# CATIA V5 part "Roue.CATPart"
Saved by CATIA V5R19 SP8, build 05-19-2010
Part number: Roue
Bounding box of the stored display mesh (mm): x -500 to 275, y -874.961 to 874.961, z -874.961 to 874.961
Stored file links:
  C:\Users\rcousturie\Desktop\EU_thinkMotion\iao\IAO_MMS_Groupe1\flacan\flacan\flacan\Roue.CATPart
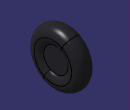
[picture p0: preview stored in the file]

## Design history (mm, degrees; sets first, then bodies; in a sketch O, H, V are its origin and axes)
Body1 (main body)
  Sketch1 on yz-plane, origin (0, 0, 0), H (0, 1, 0), V (0, 0, 1)
    circle A1 centre (0, 0) radius 600
    radius A1 = 600
  Pad1: profile Sketch1, direction (1, 0, 0), length 175, opposite side length 175
  Sketch2 on zx-plane, origin (0, 0, 0), H (-1, 0, 0), V (0, 0, 1)
    circle A1 centre (0, 600) radius 275
    point P1 (0, 600)
    radius A1 = 275
    distance P1 H = 600
    coincidence: P1 V
  Shaft1: profile Sketch2, axis Sketch2.H, angle 360
  Sketch3 on start face of Pad1, origin (-175, 0, 0), H (0, -1, 0), V (0, 0, 1)
    circle A1 centre (0, 0) radius 175
    radius A1 = 175
  Pad2: profile Sketch3, direction (-1, 0, 0), length 150
  Sketch4 on end face of Pad2, origin (-325, 0, 0), H (0, -1, 0), V (0, 0, 1)
    circle A1 centre (0, 0) radius 87.5
    point P1 (-87.5, 0)
    radius A1 = 87.5
    coincidence: A1 P1, P1 H
  Pad3: profile Sketch4, direction (-1, 0, 0), length 175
